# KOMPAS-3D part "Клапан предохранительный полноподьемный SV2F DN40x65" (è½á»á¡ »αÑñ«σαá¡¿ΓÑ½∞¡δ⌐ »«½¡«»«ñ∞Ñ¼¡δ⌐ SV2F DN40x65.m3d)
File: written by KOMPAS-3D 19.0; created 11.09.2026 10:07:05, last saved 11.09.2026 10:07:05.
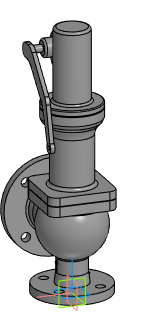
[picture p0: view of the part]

Document properties: Автор: elist; Организация: HP; Полное имя файла: Z:\3.Личные\sachek\Dendor\_3D для проектировщиков\5.9 SV2F. Клапан предохранительный полноподьемный\SV2F_STP\Клапан предохранительный полноподьемный SV2F DN40x65.m3d

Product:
- Part/product: Клапан предохранительный полноподьемный SV2F DN40x65

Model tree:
1. Операция без истории:1  (labels: Клапан предохранительный полноподьемный SV2F DN40x65)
